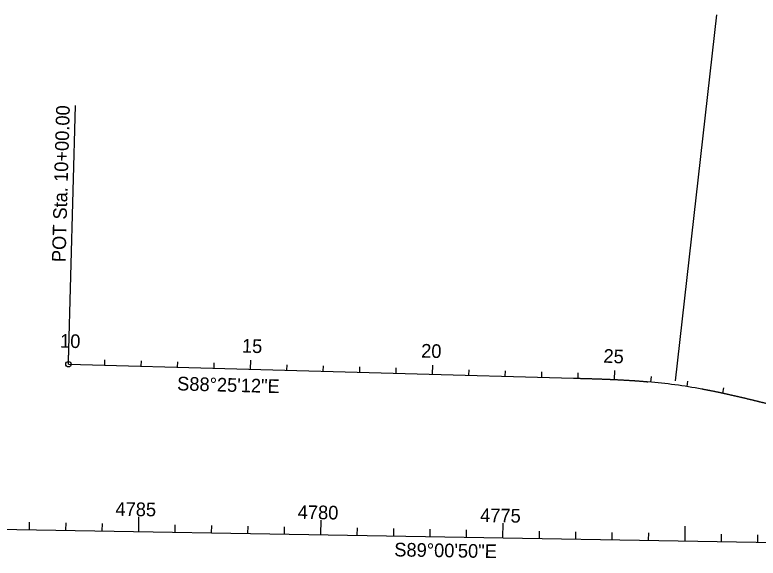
# Model space of a CAD drawing. Extents: x 1280727 to 1452510, y 526233 to 601451.
# Drawn here: x 1437617 to 1439658, y 591480 to 592971 of the extents above; entities that cross this region are included whole.
import ezdxf

# ---------------------------------------------------------------- set-up
doc = ezdxf.new("R2010")
doc.units = 0
for name, color, linetype in [('Level 63', 7, 'Continuous'), ('RW_X_CL', 7, 'Continuous'), ('RW_X_CL_500_Stations', 7, 'Continuous'), ('SH_Text', 7, 'Continuous')]:
    doc.layers.add(name, color=color, linetype=linetype)

msp = doc.modelspace()

# ---------------------------------------------------------------- linework, layer by layer
at = {"layer": 'Level 63'}
msp.add_line((1439431, 591966.4), (1439544.7, 592971.3), dxfattribs=at)
at = {"layer": 'RW_X_CL'}
for p, q in [((1437764.3, 592012.4), (1439150.7, 591974.1)), ((1435657.7, 591592.8), (1440508.2, 591509.3))]:
    msp.add_line(p, q, dxfattribs=at)
msp.add_arc((1439208, 590333.8), 1637, 79.6079, 84.8324, dxfattribs=at)
for points in [[(1439150.7, 591974.1), (1439153.5, 591974), (1439156.3, 591974), (1439159, 591973.9), (1439161.8, 591973.8), (1439164.6, 591973.7), (1439167.3, 591973.7), (1439170.1, 591973.6), (1439172.9, 591973.5), (1439175.6, 591973.4), (1439178.4, 591973.3), (1439181.2, 591973.3), (1439183.9, 591973.2), (1439186.7, 591973.1), (1439189.5, 591973), (1439192.3, 591972.9), (1439195, 591972.9), (1439197.8, 591972.8), (1439200.6, 591972.7), (1439203.3, 591972.6), (1439206.1, 591972.5), (1439208.9, 591972.4), (1439211.6, 591972.3), (1439214.4, 591972.2), (1439217.2, 591972.1), (1439219.9, 591972), (1439222.7, 591972), (1439225.5, 591971.9), (1439228.2, 591971.8), (1439231, 591971.7), (1439233.8, 591971.5), (1439236.6, 591971.4), (1439239.3, 591971.3), (1439242.1, 591971.2), (1439244.9, 591971.1), (1439247.6, 591971), (1439250.4, 591970.9), (1439253.2, 591970.8), (1439255.9, 591970.6), (1439258.7, 591970.5), (1439261.5, 591970.4), (1439264.2, 591970.3), (1439267, 591970.1), (1439269.8, 591970), (1439272.5, 591969.9), (1439275.3, 591969.7), (1439278.1, 591969.6), (1439280.8, 591969.4), (1439283.6, 591969.3), (1439286.4, 591969.1), (1439289.1, 591969), (1439291.9, 591968.8), (1439294.7, 591968.7), (1439297.4, 591968.5), (1439300.2, 591968.3), (1439303, 591968.2), (1439305.7, 591968), (1439308.5, 591967.8), (1439311.2, 591967.6), (1439314, 591967.4), (1439316.8, 591967.3), (1439319.5, 591967.1), (1439322.3, 591966.9), (1439325.1, 591966.7), (1439327.8, 591966.5), (1439330.6, 591966.3), (1439333.4, 591966), (1439336.1, 591965.8), (1439338.9, 591965.6), (1439341.6, 591965.4), (1439344.4, 591965.2), (1439347.2, 591964.9), (1439349.9, 591964.7), (1439352.7, 591964.4), (1439355.4, 591964.2)], [(1439703.2, 591898.6), (1439700.5, 591899.3), (1439697.8, 591900), (1439695.1, 591900.7), (1439692.4, 591901.3), (1439689.7, 591902), (1439687, 591902.7), (1439684.3, 591903.3), (1439681.7, 591904), (1439679, 591904.7), (1439676.3, 591905.3), (1439673.6, 591906), (1439670.9, 591906.7), (1439668.2, 591907.3), (1439665.5, 591908), (1439662.8, 591908.6), (1439660.1, 591909.3), (1439657.5, 591910), (1439654.8, 591910.6), (1439652.1, 591911.3), (1439649.4, 591911.9), (1439646.7, 591912.6), (1439644, 591913.3), (1439641.3, 591913.9), (1439638.6, 591914.6), (1439635.9, 591915.2), (1439633.2, 591915.9), (1439630.5, 591916.5), (1439627.8, 591917.2), (1439625.1, 591917.8), (1439622.5, 591918.4), (1439619.8, 591919.1), (1439617.1, 591919.7), (1439614.4, 591920.4), (1439611.7, 591921), (1439609, 591921.6), (1439606.3, 591922.3), (1439603.6, 591922.9), (1439600.9, 591923.5), (1439598.2, 591924.1), (1439595.5, 591924.8), (1439592.8, 591925.4), (1439590.1, 591926), (1439587.4, 591926.6), (1439584.7, 591927.2), (1439582, 591927.8), (1439579.3, 591928.4), (1439576.6, 591929), (1439573.9, 591929.6), (1439571.2, 591930.2), (1439568.4, 591930.8), (1439565.7, 591931.4), (1439563, 591932), (1439560.3, 591932.6), (1439557.6, 591933.2), (1439554.9, 591933.7), (1439552.2, 591934.3), (1439549.5, 591934.9), (1439546.8, 591935.5), (1439544.1, 591936), (1439541.4, 591936.6), (1439538.6, 591937.1), (1439535.9, 591937.7), (1439533.2, 591938.2), (1439530.5, 591938.8), (1439527.8, 591939.3), (1439525.1, 591939.9), (1439522.3, 591940.4), (1439519.6, 591940.9), (1439516.9, 591941.4), (1439514.2, 591942), (1439511.5, 591942.5), (1439508.7, 591943), (1439506, 591943.5), (1439503.3, 591944)]]:
    msp.add_spline(points, degree=3, dxfattribs=at)
at = {"layer": 'RW_X_CL_500_Stations'}
for p, q in [((1437764.3, 592012.4), (1437765, 592037.4)), ((1437864.3, 592009.6), (1437864.7, 592024.6)), ((1437964.2, 592006.9), (1437964.6, 592021.8)), ((1438064.2, 592004.1), (1438064.6, 592019.1)), ((1438164.2, 592001.3), (1438164.6, 592016.3)), ((1438264.1, 591998.6), (1438264.8, 592023.6)), ((1438364.1, 591995.8), (1438364.5, 592010.8)), ((1438464, 591993.1), (1438464.5, 592008.1)), ((1438564, 591990.3), (1438564.4, 592005.3)), ((1438664, 591987.6), (1438664.4, 592002.5)), ((1438763.9, 591984.8), (1438764.6, 592009.8)), ((1438863.9, 591982), (1438864.3, 591997)), ((1438963.8, 591979.3), (1438964.3, 591994.3)), ((1439263.7, 591970.3), (1439264.9, 591995.3)), ((1439063.8, 591976.5), (1439064.2, 591991.5)), ((1439163.8, 591973.8), (1439164.2, 591988.8)), ((1439363.5, 591963.5), (1439364.9, 591978.4)), ((1439462.7, 591950.9), (1439465, 591965.7)), ((1439560.9, 591932.5), (1439564.1, 591947.1)), ((1437957.4, 591553.2), (1437958.1, 591593.2)), ((1438457.3, 591544.6), (1438458, 591584.6)), ((1437657.4, 591558.4), (1437657.8, 591578.4)), ((1437757.4, 591556.6), (1437757.7, 591576.6)), ((1437857.4, 591554.9), (1437857.7, 591574.9)), ((1438057.4, 591551.5), (1438057.7, 591571.5)), ((1438157.3, 591549.8), (1438157.7, 591569.8)), ((1438257.3, 591548), (1438257.7, 591568)), ((1438357.3, 591546.3), (1438357.7, 591566.3)), ((1438957.2, 591536), (1438957.9, 591576)), ((1439457.2, 591527.4), (1439457.8, 591567.4)), ((1438557.3, 591542.9), (1438557.6, 591562.9)), ((1438657.3, 591541.2), (1438657.6, 591561.1)), ((1438757.3, 591539.4), (1438757.6, 591559.4)), ((1438857.2, 591537.7), (1438857.6, 591557.7)), ((1439057.2, 591534.3), (1439057.6, 591554.3)), ((1439157.2, 591532.5), (1439157.5, 591552.5)), ((1439257.2, 591530.8), (1439257.5, 591550.8)), ((1439357.2, 591529.1), (1439357.5, 591549.1)), ((1439557.1, 591525.7), (1439557.5, 591545.7)), ((1439657.1, 591523.9), (1439657.5, 591543.9))]:
    msp.add_line(p, q, dxfattribs=at)
at = {"layer": 'SH_Text'}
msp.add_line((1437764.5, 592019.9), (1437783.9, 592722.4), dxfattribs=at)
msp.add_circle((1437764.3, 592012.4), 7.5, dxfattribs=at)

# ---------------------------------------------------------------- texts
at = {"layer": 'RW_X_CL_500_Stations'}
for s, rotation, p in [('10', 358.4199, (1437741, 592058)), ('15', 358.4199, (1438240.4, 592044.3)), ('20', 358.4199, (1438732.3, 592030.7)), ('25', 357.3286, (1439232.5, 592016.8)), ('4785', 359.0138, (1437893.2, 591596.5)), ('4780', 359.0138, (1438393.6, 591587.9)), ('4775', 359.0138, (1438894.4, 591579.3))]:
    msp.add_text(s, height=37.5, rotation=rotation, dxfattribs=at).set_placement(p)
at = {"layer": 'SH_Text'}
for s, rotation, p in [('POT Sta. 10+00.00', 88.4199, (1437756.4, 592292.1)), ('S88°25\'12"E', 358.4199, (1438062.4, 591940.7)), ('S89°00\'50"E', 359.0138, (1438658.7, 591484.9))]:
    msp.add_text(s, height=37.5, rotation=rotation, dxfattribs=at).set_placement(p)

doc.saveas('drawing.dxf')
